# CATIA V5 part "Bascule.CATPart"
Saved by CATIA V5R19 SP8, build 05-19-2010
Part number: Pièce 1
Bounding box of the stored display mesh (mm): x -3 to 7, y -20.269 to 27.148, z -11.723 to 81.141
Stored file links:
  F:\Projet3\Bascule.CATPart
  F:\Projet3\Produit1.CATProduct
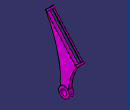
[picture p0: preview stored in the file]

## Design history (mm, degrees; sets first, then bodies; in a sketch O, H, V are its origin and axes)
Parameters
  Longueur = 10 mm
Body1 (main body)
  Sketch1 on yz-plane, origin (0, 0, 0), H (0, 1, 0), V (0, 0, 1)
    arc A1 centre (-150, 0) radius 150 from (0, 0) to (-19.9575, 74.7593) ccw
    point P2 (-19.9575, 74.7593)
    arc A2 centre (69.909, -3.303) radius 60 from (10, 0) to (20, 30) cw
    point P4 (10, 0)
    point P5 (20, 30)
    point P6 (10, 0)
    line L1 (10, 0) -> (0, 0)
    point P7 (20, 30)
    line L2 (20, 30) -> (-19.9575, 74.7593)
    point P8 (-19.9575, 74.7593)
    distance P5 L1 = 30 {= Longueur *3}
    length L2 = 60 {= Longueur *6}
    radius A1 = 150 {= Longueur *15}
    radius A2 = 60 {= Longueur *6}
    length L1 = 10 {= Longueur *1}
    distance P5 V = 20 {= Longueur *2}
    coincidence: P4 H, P6 A2, P7 A2, P8 A1, L2 P2, P7 P5, P2 P8, P4 P6
    horizontal: L1 H
    tangency: A1 V
  Pad1: profile Sketch1, direction (1, 0, 0), length 4 {= Longueur *0.4}
  Point1: (5 {= Longueur *0.5}, 0 {= Longueur *0}, 0 {= Longueur *0})
  Plane1: type OffsetPt, RefPlane end face of Pad1, RefPoint Point1
  Sketch2 on end face of Pad1, origin (4, 0, 0), H (0, 1, 0), V (0, 0, 1)
    arc A1 centre (5, -4.899) radius 7 from (0, 0) to (10, 0) cw
    point P2 (0, 0)
    point P3 (10, 0)
    reference projected point E1 (10, 0) from vertex [face of Pad1 from Sketch1.A2 | end face of Pad1 | face of Pad1 from Sketch1.L1]
    radius A1 = 7 {= Longueur *0.7}
    coincidence: P3 E1, O P2
  Pocket1: profile Sketch2, direction (-1, 0, 0), up to start face of Pad1, offset 0 {= Longueur *0}
  Sketch3 on Plane1, origin (5, 0, 0), H (0, -1, 0), V (0, 0, 1)
    circle A1 centre (-5, -4.899) radius 7
    reference projected arc E1 centre (-5, -4.899) radius 7 from (0, 0) to (-10, 0) ccw from edge [face of Pocket1 from Sketch2.A1 | start face of Pad1]
    coincidence: A1 E1
  Pad2: profile Sketch3, direction (-1, 0, 0), length 6 {= Longueur *0.6}
  Sketch4 on start face of Pad2, origin (5, 0, 0), H (0, 1, 0), V (0, 0, 1)
    circle A1 centre (5, -4.899) radius 4
    reference projected circle E1 centre (5, -4.899) radius 7 from edge [start face of Pad2 | face of Pad2 from Sketch3.A1]
    radius A1 = 4 {= Longueur *0.4}
    concentricity: A1 E1
  Pocket2: profile Sketch4, direction (-1, 0, 0), up to end face of Pad2, offset 0 {= Longueur *0}
  Point2: type OnCurve, Support edge [face of Pad1 from Sketch1.L2 | face of Pad1 from Sketch1.A2], Length 2 {= Longueur *0.2}
  Plane2: type Normal, Curve edge [start face of Pad1 | face of Pad1 from Sketch1.L2], RefPoint Point2
  Sketch5 on Plane2, origin (0, -6.0339, 6.759), H (1, 0, 0), V (0, 0.746, 0.666)
    arc A1 centre (2, 39.4811) radius 5 from (4, 34.8985) to (0, 34.8985) cw
    point P2 (4, 34.8985)
    point P3 (0, 34.8985)
    reference projected point E1 (4, 34.8985) from vertex [face of Pad1 from Sketch1.A1 | end face of Pad1 | face of Pad1 from Sketch1.L2]
    reference projected point E2 (0, 34.8985) from vertex [face of Pad1 from Sketch1.A1 | start face of Pad1 | face of Pad1 from Sketch1.L2]
    radius A1 = 5 {= Longueur *0.5}
    coincidence: P2 E1, P3 E2
  Pocket3: profile Sketch5, direction (0, -0.666, 0.746), through (limit type 6), offset 0 {= Longueur *0}
  Sketch6 on Plane2, origin (0, -6.0339, 6.759), H (1, 0, 0), V (0, 0.746, 0.666)
    circle A1 centre (2, 39.4809) radius 4.9998
    reference projected arc E1 centre (2, 39.4809) radius 4.9998 from (0.3334, 34.767) to (3.6666, 34.767) ccw from edge [face of Pocket3 from Sketch5.A1 | face of Pad1 from Sketch1.A1]
    coincidence: E1 A1
  Pad3: profile Sketch6, direction (0, -0.666, 0.746), length 2 {= Longueur *0.2}
  Sketch7 on start face of Pad3, origin (0, -6.0339, 6.759), H (-1, 0, 0), V (0, 0.746, 0.666)
    circle A1 centre (-2, 39.4809) radius 1
    reference projected circle E1 centre (-2, 39.4809) radius 4.9998 from edge [start face of Pad3 | face of Pad3 from Sketch6.A1]
    radius A1 = 1 {= Longueur *0.1}
    concentricity: A1 E1
  Pocket4: profile Sketch7, direction (0, -0.666, 0.746), up to end face of Pad3, offset 0 {= Longueur *0}
  Sketch8 on end face of Pad3, origin (0, -7.3658, 8.251), H (1, 0, 0), V (0, 0.746, 0.666)
    arc A1 centre (2, 39.4809) radius 4.9998 from (3, 44.3798) to (1, 44.3798) ccw
    line L1 (3, 44.3798) -> (3, 43.3538)
    arc A2 centre (2, 39.4809) radius 3.9998 from (3, 43.3538) to (1, 43.3538) ccw
    line L2 (1, 43.3538) -> (1, 44.3798)
    reference projected circle E1 centre (2, 39.4809) radius 4.9998 from edge [face of Pad3 from Sketch6.A1 | end face of Pad3]
    distance L1 L2 = 2 {= Longueur *0.2}
    distance L2 V = 1 {= Longueur *0.1}
    distance A2 A1 = 1 {= Longueur *0.1}
    vertical: L1 V
    coincidence: A1 E1
    concentricity: A2 A1
  Pad4: profile Sketch8, direction (0, -0.666, 0.746), length 56 {= Longueur *5.6}
  Sketch9 on end face of Pad4, origin (0, -44.6595, 50.0264), H (1, 0, 0), V (0, 0.746, 0.666)
    circle A1 centre (2, 39.4809) radius 4.9998
    reference projected arc E1 centre (2, 39.4809) radius 4.9998 from (0, 34.8985) to (4, 34.8985) ccw from edge [face of Pad1 from Sketch1.A1 | face of Pocket3 from Sketch5.A1]
    coincidence: E1 A1
  Pad5: profile Sketch9, direction (0, -0.666, 0.746), length 2 {= Longueur *0.2}
  Sketch10 on end face of Pad5, origin (0, -45.9914, 51.5183), H (1, 0, 0), V (0, 0.746, 0.666)
    circle A1 centre (2, 39.4809) radius 1
    reference projected circle E1 centre (2, 39.4809) radius 4.9998 from edge [face of Pad5 from Sketch9.A1 | end face of Pad5]
    radius A1 = 1 {= Longueur *0.1}
    concentricity: A1 E1
  Pocket5: profile Sketch10, direction (0, 0.666, -0.746), up to start face of Pad5, offset 0 {= Longueur *0}
  Sketch11 on end face of Pad3, origin (0, -7.3658, 8.251), H (1, 0, 0), V (0, 0.746, 0.666)
    circle A1 centre (2, 39.4809) radius 4.9998
    reference projected arc E1 centre (2, 39.4809) radius 4.9998 from (0.3334, 34.767) to (3.6666, 34.767) ccw from edge [face of Pocket3 from Sketch5.A1 | face of Pad1 from Sketch1.A1]
    coincidence: E1 A1
  Pad6: profile Sketch11, direction (0, -0.666, 0.746), length 2 {= Longueur *0.2}
Current feature: Pocket5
